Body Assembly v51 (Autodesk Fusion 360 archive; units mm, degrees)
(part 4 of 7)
sketch "Sketch22" plane through (0, 0, 30.35) normal (0, 0, 1) x axis (-1, 0, 0)
  line L1 (-73.525, 79.5) -> (-73.525, 184)
  line L2 (-59.525, 79.5) -> (-73.525, 79.5)
  line L3 (-59.525, 174.475) -> (-59.525, 79.5)
  line L4 (1.475, 174.475) -> (-59.525, 174.475)
  line L5 (1.475, 79.5) -> (1.475, 174.475)
  line L6 (37.7, 79.5) -> (1.475, 79.5)
  line L7 (37.7, 158.6) -> (37.7, 79.5)
  line L8 (-84.3454, 196.7) -> (-0.4, 196.7)
  line L9 (-122.4454, 79.5) -> (-122.4454, 158.6)
  line L10 (-109.7454, 79.5) -> (-122.4454, 79.5)
  line L11 (-109.7454, 158.6) -> (-109.7454, 79.5)
  line L12 (-73.525, 184) -> (-84.3454, 184)
  line L13 (-59.525, 18.175) -> (-109.7454, 18.175)
  line L14 (-59.525, 79.5) -> (-59.525, 18.175)
  line L15 (-122.4454, 79.5) -> (-59.525, 79.5)
  line L16 (-122.4454, 0.3904) -> (-122.4454, 79.5)
  line L17 (-0.4, -37.7096) -> (-84.3454, -37.7096)
  line L18 (37.7, 79.5) -> (37.7, 0.3904)
  line L19 (1.475, 79.5) -> (37.7, 79.5)
  line L20 (1.475, 18.175) -> (1.475, 79.5)
  line L21 (25, 18.175) -> (1.475, 18.175)
  line L22 (25, 0.3904) -> (25, 18.175)
  line L23 (-84.3454, -25.0096) -> (-0.4, -25.0096)
  line L24 (-109.7454, 18.175) -> (-109.7454, 0.3904)
  line L25 (-0.4, 190.35) -> (-84.35, 190.35)
  line L26 (14.4492, 185.5408) -> (15.1755, 186.267)
  line L27 (27.267, 174.1755) -> (26.5408, 173.4492)
  line L28 (31.35, 116.35) -> (31.35, 158.6)
  line L29 (29.15, 116.35) -> (31.35, 116.35)
  line L30 (31.35, 99.25) -> (29.15, 99.25)
  line L31 (31.35, 79.5) -> (31.35, 99.25)
  line L32 (37.7, 79.5) -> (31.35, 79.5)
  line L33 (37.7, 158.6) -> (37.7, 79.5)
  line L34 (-84.35, 196.7) -> (-0.4, 196.7)
  line L35 (-122.45, 79.5) -> (-122.45, 158.6)
  line L36 (-116.1, 79.5) -> (-122.45, 79.5)
  line L37 (-116.1, 99.25) -> (-116.1, 79.5)
  line L38 (-113.9, 99.25) -> (-116.1, 99.25)
  line L39 (-116.1, 116.35) -> (-113.9, 116.35)
  line L40 (-116.1, 158.6) -> (-116.1, 116.35)
  line L41 (-111.2908, 173.4492) -> (-112.017, 174.1755)
  line L42 (-99.9255, 186.267) -> (-99.1992, 185.5408)
  line L43 (-116.1, 79.5) -> (-116.1, 59.75)
  line L44 (-122.45, 79.5) -> (-116.1, 79.5)
  line L45 (-122.45, 0.4) -> (-122.45, 79.5)
  line L46 (-0.4, -37.7) -> (-84.35, -37.7)
  line L47 (37.7, 79.5) -> (37.7, 0.4)
  line L48 (31.35, 79.5) -> (37.7, 79.5)
  line L49 (31.35, 59.75) -> (31.35, 79.5)
  line L50 (29.15, 59.75) -> (31.35, 59.75)
  line L51 (31.35, 42.65) -> (29.15, 42.65)
  line L52 (31.35, 0.4) -> (31.35, 42.65)
  line L53 (26.5408, -14.4492) -> (27.267, -15.1755)
  line L54 (15.1755, -27.267) -> (14.4492, -26.5408)
  line L55 (-84.35, -31.35) -> (-0.4, -31.35)
  line L56 (-99.1992, -26.5408) -> (-99.9255, -27.267)
  line L57 (-112.017, -15.1755) -> (-111.2908, -14.4492)
  line L58 (-116.1, 42.65) -> (-116.1, 0.4)
  line L59 (-113.9, 42.65) -> (-116.1, 42.65)
  line L60 (-116.1, 59.75) -> (-113.9, 59.75)
  arc A1 centre (-0.4, 158.6) radius 38.1 clockwise from (-0.4, 196.7) to (37.7, 158.6)
  arc A2 centre (-84.3454, 158.6) radius 38.1 clockwise from (-122.4454, 158.6) to (-84.3454, 196.7)
  arc A3 centre (-84.3454, 158.6) radius 25.4 clockwise from (-109.7454, 158.6) to (-84.3454, 184)
  arc A4 centre (-113.9, 107.8) radius 8.55 clockwise from (-113.9, 116.35) to (-113.9, 99.25)
  arc A5 centre (-105.245, 179.495) radius 8.55 clockwise from (-99.1992, 185.5408) to (-111.2908, 173.4492)
  arc A6 centre (-105.245, -20.495) radius 8.55 clockwise from (-111.2908, -14.4492) to (-99.1992, -26.5408)
  arc A7 centre (20.495, -20.495) radius 8.55 clockwise from (14.4492, -26.5408) to (26.5408, -14.4492)
  arc A8 centre (-84.3454, 0.3904) radius 38.1 clockwise from (-84.3454, -37.7096) to (-122.4454, 0.3904)
  arc A9 centre (-0.4, 0.3904) radius 38.1 clockwise from (37.7, 0.3904) to (-0.4, -37.7096)
  arc A10 centre (-0.4, 0.3904) radius 25.4 clockwise from (25, 0.3904) to (-0.4, -25.0096)
  arc A11 centre (-84.3454, 0.3904) radius 25.4 clockwise from (-84.3454, -25.0096) to (-109.7454, 0.3904)
  circle C1 centre (-105.245, 179.495) radius 2.2
  circle C2 centre (20.495, 179.495) radius 2.2
  circle C3 centre (-113.9, 107.8) radius 2.2
  circle C4 centre (29.15, 107.8) radius 2.2
  arc A12 centre (-84.35, 158.6) radius 31.75 clockwise from (-99.9255, 186.267) to (-84.35, 190.35)
  arc A13 centre (-0.4, 158.6) radius 31.75 clockwise from (-0.4, 190.35) to (15.1755, 186.267)
  arc A14 centre (20.495, 179.495) radius 8.55 clockwise from (26.5408, 173.4492) to (14.4492, 185.5408)
  arc A15 centre (-0.4, 158.6) radius 31.75 clockwise from (27.267, 174.1755) to (31.35, 158.6)
  arc A16 centre (29.15, 107.8) radius 8.55 clockwise from (29.15, 99.25) to (29.15, 116.35)
  arc A17 centre (-0.4, 158.6) radius 38.1 clockwise from (-0.4, 196.7) to (37.7, 158.6)
  arc A18 centre (-84.35, 158.6) radius 38.1 clockwise from (-122.45, 158.6) to (-84.35, 196.7)
  arc A19 centre (-113.9, 107.8) radius 8.55 clockwise from (-113.9, 116.35) to (-113.9, 99.25)
  arc A20 centre (-84.35, 158.6) radius 31.75 clockwise from (-116.1, 158.6) to (-112.017, 174.1755)
  arc A21 centre (-105.245, 179.495) radius 8.55 clockwise from (-99.1992, 185.5408) to (-111.2908, 173.4492)
  arc A22 centre (-84.35, 0.4) radius 38.1 clockwise from (-84.35, -37.7) to (-122.45, 0.4)
  arc A23 centre (-0.4, 0.4) radius 38.1 clockwise from (37.7, 0.4) to (-0.4, -37.7)
  arc A24 centre (29.15, 51.2) radius 8.55 clockwise from (29.15, 42.65) to (29.15, 59.75)
  arc A25 centre (-0.4, 0.4) radius 31.75 clockwise from (31.35, 0.4) to (27.267, -15.1755)
  arc A26 centre (20.495, -20.495) radius 8.55 clockwise from (14.4492, -26.5408) to (26.5408, -14.4492)
  arc A27 centre (-0.4, 0.4) radius 31.75 clockwise from (15.1755, -27.267) to (-0.4, -31.35)
  arc A28 centre (-84.35, 0.4) radius 31.75 clockwise from (-84.35, -31.35) to (-99.9255, -27.267)
  arc A29 centre (-105.245, -20.495) radius 8.55 clockwise from (-111.2908, -14.4492) to (-99.1992, -26.5408)
  arc A30 centre (-84.35, 0.4) radius 31.75 clockwise from (-112.017, -15.1755) to (-116.1, 0.4)
  arc A31 centre (-113.9, 51.2) radius 8.55 clockwise from (-113.9, 59.75) to (-113.9, 42.65)
  circle C5 centre (-105.245, -20.495) radius 2.2
  circle C6 centre (20.495, -20.495) radius 2.2
  circle C7 centre (29.15, 51.2) radius 2.2
  circle C8 centre (-113.9, 51.2) radius 2.2
extrude "Extrude44" add sketch "Sketch22" profile of L11 A3 A4 A5 A6 A7 A10 A11 against normal blind 6.35
hole "Hole5" HoleDepth 10.0076 HoleDiameter 3.4 (= "m3screwdiam") TipAngle 180
position "Position22"
sketch "Sketch23" plane through (0, 0, -1.65) normal (0, 0, 1) x axis (-1, 0, 0)
  line L1 (-113.9, 59.75) -> (-116.1, 59.75)
  line L2 (-116.1, 42.65) -> (-113.9, 42.65)
  line L3 (-116.1, 0.4) -> (-116.1, 42.65)
  line L4 (-111.2908, -14.4492) -> (-112.017, -15.1755)
  line L5 (-99.9255, -27.267) -> (-99.1992, -26.5408)
  line L6 (-0.4, -31.35) -> (-84.35, -31.35)
  line L7 (14.4492, -26.5408) -> (15.1755, -27.267)
  line L8 (27.267, -15.1755) -> (26.5408, -14.4492)
  line L9 (31.35, 42.65) -> (31.35, 0.4)
  line L10 (29.15, 42.65) -> (31.35, 42.65)
  line L11 (31.35, 59.75) -> (29.15, 59.75)
  line L12 (31.35, 79.5) -> (31.35, 59.75)
  line L13 (-116.1, 79.5) -> (31.35, 79.5)
  line L14 (-116.1, 59.75) -> (-116.1, 79.5)
  line L15 (4.625, 25) -> (9.125, 20.5)
  line L16 (-36.375, 25) -> (4.625, 25)
  line L17 (-40.875, 20.5) -> (-36.375, 25)
  line L18 (-40.875, -20.5) -> (-40.875, 20.5)
  line L19 (-36.375, -25) -> (-40.875, -20.5)
  line L20 (4.625, -25) -> (-36.375, -25)
  line L21 (9.125, -20.5) -> (4.625, -25)
  line L22 (9.125, 20.5) -> (9.125, -20.5)
  line L23 (4.625, 78) -> (9.125, 73.5)
  line L24 (-36.375, 78) -> (4.625, 78)
  line L25 (-40.875, 73.5) -> (-36.375, 78)
  line L26 (-40.875, 32.5) -> (-40.875, 73.5)
  line L27 (-36.375, 28) -> (-40.875, 32.5)
  line L28 (4.625, 28) -> (-36.375, 28)
  line L29 (9.125, 32.5) -> (4.625, 28)
  line L30 (9.125, 73.5) -> (9.125, 32.5)
  line L31 (-48.375, 78) -> (-43.875, 73.5)
  line L32 (-89.375, 78) -> (-48.375, 78)
  line L33 (-93.875, 73.5) -> (-89.375, 78)
  line L34 (-93.875, 32.5) -> (-93.875, 73.5)
  line L35 (-89.375, 28) -> (-93.875, 32.5)
  line L36 (-48.375, 28) -> (-89.375, 28)
  line L37 (-43.875, 32.5) -> (-48.375, 28)
  line L38 (-43.875, 73.5) -> (-43.875, 32.5)
  line L39 (-48.375, 131) -> (-43.875, 126.5)
  line L40 (-89.375, 131) -> (-48.375, 131)
  line L41 (-93.875, 126.5) -> (-89.375, 131)
  line L42 (-93.875, 85.5) -> (-93.875, 126.5)
  line L43 (-89.375, 81) -> (-93.875, 85.5)
  line L44 (-48.375, 81) -> (-89.375, 81)
  line L45 (-43.875, 85.5) -> (-48.375, 81)
  line L46 (-43.875, 126.5) -> (-43.875, 85.5)
  line L47 (4.625, 131) -> (9.125, 126.5)
  line L48 (-36.375, 131) -> (4.625, 131)
  line L49 (-40.875, 126.5) -> (-36.375, 131)
  line L50 (-40.875, 85.5) -> (-40.875, 126.5)
  line L51 (-36.375, 81) -> (-40.875, 85.5)
  line L52 (4.625, 81) -> (-36.375, 81)
  line L53 (9.125, 85.5) -> (4.625, 81)
  line L54 (9.125, 126.5) -> (9.125, 85.5)
  line L55 (-48.375, 184) -> (-43.875, 179.5)
  line L56 (-89.375, 184) -> (-48.375, 184)
  line L57 (-93.875, 179.5) -> (-89.375, 184)
  line L58 (-93.875, 138.5) -> (-93.875, 179.5)
  line L59 (-89.375, 134) -> (-93.875, 138.5)
  line L60 (-48.375, 134) -> (-89.375, 134)
  line L61 (-43.875, 138.5) -> (-48.375, 134)
  line L62 (-43.875, 179.5) -> (-43.875, 138.5)
  line L63 (4.625, 184) -> (9.125, 179.5)
  line L64 (-36.375, 184) -> (4.625, 184)
  line L65 (-40.875, 179.5) -> (-36.375, 184)
  line L66 (-40.875, 138.5) -> (-40.875, 179.5)
  line L67 (-36.375, 134) -> (-40.875, 138.5)
  line L68 (4.625, 134) -> (-36.375, 134)
  line L69 (9.125, 138.5) -> (4.625, 134)
  line L70 (9.125, 179.5) -> (9.125, 138.5)
  line L71 (-48.375, 25) -> (-43.875, 20.5)
  line L72 (-89.375, 25) -> (-48.375, 25)
  line L73 (-93.875, 20.5) -> (-89.375, 25)
  line L74 (-93.875, -20.5) -> (-93.875, 20.5)
  line L75 (-89.375, -25) -> (-93.875, -20.5)
  line L76 (-48.375, -25) -> (-89.375, -25)
  line L77 (-43.875, -20.5) -> (-48.375, -25)
  line L78 (-43.875, 20.5) -> (-43.875, -20.5)
  arc A1 centre (-113.9, 51.2) radius 8.55 clockwise from (-113.9, 59.75) to (-113.9, 42.65)
  arc A2 centre (-84.35, 0.4) radius 31.75 clockwise from (-112.017, -15.1755) to (-116.1, 0.4)
  arc A3 centre (-105.245, -20.495) radius 8.55 clockwise from (-111.2908, -14.4492) to (-99.1992, -26.5408)
  arc A4 centre (-84.35, 0.4) radius 31.75 clockwise from (-84.35, -31.35) to (-99.9255, -27.267)
  arc A5 centre (-0.4, 0.4) radius 31.75 clockwise from (15.1755, -27.267) to (-0.4, -31.35)
  arc A6 centre (20.495, -20.495) radius 8.55 clockwise from (14.4492, -26.5408) to (26.5408, -14.4492)
  arc A7 centre (-0.4, 0.4) radius 31.75 clockwise from (31.35, 0.4) to (27.267, -15.1755)
  arc A8 centre (29.15, 51.2) radius 8.55 clockwise from (29.15, 42.65) to (29.15, 59.75)
  circle C1 centre (-35.875, -20) radius 1.5
  circle C2 centre (-35.875, 20) radius 1.5
  circle C3 centre (4.125, -20) radius 1.5
  circle C4 centre (4.125, 20) radius 1.5
  circle C5 centre (-29.625, 0) radius 1.5
  circle C6 centre (-2.125, 0) radius 1.5
  circle C7 centre (-35.875, 33) radius 1.5
  circle C8 centre (-35.875, 73) radius 1.5
  circle C9 centre (4.125, 33) radius 1.5
  circle C10 centre (4.125, 73) radius 1.5
  circle C11 centre (-29.625, 53) radius 1.5
  circle C12 centre (-2.125, 53) radius 1.5
  circle C13 centre (-88.875, 33) radius 1.5
  circle C14 centre (-88.875, 73) radius 1.5
  circle C15 centre (-48.875, 33) radius 1.5
  circle C16 centre (-48.875, 73) radius 1.5
  circle C17 centre (-82.625, 53) radius 1.5
  circle C18 centre (-55.125, 53) radius 1.5
  circle C19 centre (-88.875, 86) radius 1.5
  circle C20 centre (-88.875, 126) radius 1.5
  circle C21 centre (-48.875, 86) radius 1.5
  circle C22 centre (-48.875, 126) radius 1.5
  circle C23 centre (-82.625, 106) radius 1.5
  circle C24 centre (-55.125, 106) radius 1.5
  circle C25 centre (-35.875, 86) radius 1.5
  circle C26 centre (-35.875, 126) radius 1.5
  circle C27 centre (4.125, 86) radius 1.5
  circle C28 centre (4.125, 126) radius 1.5
  circle C29 centre (-29.625, 106) radius 1.5
  circle C30 centre (-2.125, 106) radius 1.5
  circle C31 centre (-88.875, 139) radius 1.5
  circle C32 centre (-88.875, 179) radius 1.5
  circle C33 centre (-48.875, 139) radius 1.5
  circle C34 centre (-48.875, 179) radius 1.5
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hole "Hole6" HoleDepth 38.1 HoleDiameter 4.4 (= "threadedinsertdiam") TipAngle 180
sketch "Sketch25" plane through (0, 0, 30.35) normal (0, 0, 1) x axis (-1, 0, 0)
  line L1 (-73.525, 79.5) -> (-73.525, 184)
  line L2 (-59.525, 79.5) -> (-73.525, 79.5)
  line L3 (-59.525, 174.475) -> (-59.525, 79.5)
  line L4 (1.475, 174.475) -> (-59.525, 174.475)
  line L5 (1.475, 79.5) -> (1.475, 174.475)
  line L6 (37.7, 79.5) -> (1.475, 79.5)
  line L7 (37.7, 158.6) -> (37.7, 79.5)
  line L8 (-84.3454, 196.7) -> (-0.4, 196.7)
  line L9 (-122.4454, 79.5) -> (-122.4454, 158.6)
  line L10 (-109.7454, 79.5) -> (-122.4454, 79.5)
  line L11 (-109.7454, 100.3273) -> (-109.7454, 79.5)
  line L12 (-109.7454, 158.6) -> (-109.7454, 115.2727)
  line L13 (-73.525, 184) -> (-84.3454, 184)
  circle C1 centre (-105.245, 179.495) radius 1.7
  circle C2 centre (20.495, 179.495) radius 1.7
  circle C3 centre (29.15, 107.8) radius 1.7
  circle C4 centre (-113.9, 107.8) radius 1.7
  arc A1 centre (-0.4, 158.6) radius 38.1 clockwise from (-0.4, 196.7) to (37.7, 158.6)
  arc A2 centre (-84.3454, 158.6) radius 38.1 clockwise from (-122.4454, 158.6) to (-84.3454, 196.7)
  arc A3 centre (-113.9, 107.8) radius 8.55 clockwise from (-109.7454, 115.2727) to (-109.7454, 100.3273)
  arc A4 centre (-84.3454, 158.6) radius 25.4 clockwise from (-109.7454, 158.6) to (-106.4925, 171.0365)
  arc A5 centre (-105.245, 179.495) radius 8.55 clockwise from (-96.7868, 180.7443) to (-106.4925, 171.0365)
  arc A6 centre (-84.3454, 158.6) radius 25.4 clockwise from (-96.7868, 180.7443) to (-84.3454, 184)
  circle C5 centre (7.825, 148.425) radius 1.5
  circle C6 centre (-65.875, 148.425) radius 1.5
  circle C7 centre (-65.875, 96.325) radius 1.5
  circle C8 centre (7.825, 96.325) radius 1.5
  circle C9 centre (7.825, 44.225) radius 1.5
  circle C10 centre (-65.875, 44.225) radius 1.5
hole "Hole7" HoleDepth 22.86 HoleDiameter 4.4 (= "threadedinsertdiam") TipAngle 180
move "Move1"
extrude "Extrude48" new body of existing geometry blind 19.05
extrude "Extrude49" new body of existing geometry blind 16.51
combine "Combine10"
combine "Combine11"
mirror "Mirror6" mirrorStitchTolerance 0.1016
mirror "Mirror7" mirrorStitchTolerance 0.1016
combine "Combine12"
combine "Combine13"
sketch "Sketch26" plane through (0, 0, 30.35) normal (0, 0, -1) x axis (1, 0, 0)
  line L1 (113.9, 116.35) -> (116.1, 116.35)
  line L2 (116.1, 99.25) -> (113.9, 99.25)
  line L3 (116.1, 79.5) -> (116.1, 99.25)
  line L4 (122.45, 79.5) -> (116.1, 79.5)
  line L5 (122.45, 158.6) -> (122.45, 79.5)
  line L6 (0.4, 196.7) -> (84.35, 196.7)
  line L7 (-37.7, 79.5) -> (-37.7, 158.6)
  line L8 (-31.35, 79.5) -> (-37.7, 79.5)
  line L9 (-31.35, 99.25) -> (-31.35, 79.5)
  line L10 (-29.15, 99.25) -> (-31.35, 99.25)
  line L11 (-31.35, 116.35) -> (-29.15, 116.35)
  line L12 (-31.35, 158.6) -> (-31.35, 116.35)
  line L13 (-26.5408, 173.4492) -> (-27.267, 174.1755)
  line L14 (-15.1755, 186.267) -> (-14.4492, 185.5408)
  line L15 (84.35, 190.35) -> (0.4, 190.35)
  line L16 (99.1992, 185.5408) -> (99.9255, 186.267)
  line L17 (112.017, 174.1755) -> (111.2908, 173.4492)
  line L18 (116.1, 116.35) -> (116.1, 158.6)
  line L19 (113.9, 59.75) -> (116.1, 59.75)
  line L20 (116.1, 42.65) -> (113.9, 42.65)
  line L21 (116.1, 0.4) -> (116.1, 42.65)
  line L22 (111.2908, -14.4492) -> (112.017, -15.1755)
  line L23 (99.9255, -27.267) -> (99.1992, -26.5408)
  line L24 (0.4, -31.35) -> (84.35, -31.35)
  line L25 (-14.4492, -26.5408) -> (-15.1755, -27.267)
  line L26 (-27.267, -15.1755) -> (-26.5408, -14.4492)
  line L27 (-31.35, 42.65) -> (-31.35, 0.4)
  line L28 (-29.15, 42.65) -> (-31.35, 42.65)
  line L29 (-31.35, 59.75) -> (-29.15, 59.75)
  line L30 (-31.35, 79.5) -> (-31.35, 59.75)
  line L31 (-37.7, 79.5) -> (-31.35, 79.5)
  line L32 (-37.7, 0.4) -> (-37.7, 79.5)
  line L33 (84.35, -37.7) -> (0.4, -37.7)
  line L34 (122.45, 79.5) -> (122.45, 0.4)
  line L35 (116.1, 79.5) -> (122.45, 79.5)
  line L36 (116.1, 59.75) -> (116.1, 79.5)
  circle C1 centre (113.9, 107.8) radius 2.2
  circle C2 centre (105.245, 179.495) radius 2.2
  circle C3 centre (-20.495, 179.495) radius 2.2
  arc A1 centre (113.9, 107.8) radius 8.55 clockwise from (113.9, 99.25) to (113.9, 116.35)
  arc A2 centre (84.35, 158.6) radius 38.1 clockwise from (84.35, 196.7) to (122.45, 158.6)
  arc A3 centre (0.4, 158.6) radius 38.1 clockwise from (-37.7, 158.6) to (0.4, 196.7)
  arc A4 centre (-29.15, 107.8) radius 8.55 clockwise from (-29.15, 116.35) to (-29.15, 99.25)
  arc A5 centre (0.4, 158.6) radius 31.75 clockwise from (-31.35, 158.6) to (-27.267, 174.1755)
  arc A6 centre (-20.495, 179.495) radius 8.55 clockwise from (-14.4492, 185.5408) to (-26.5408, 173.4492)
  arc A7 centre (0.4, 158.6) radius 31.75 clockwise from (-15.1755, 186.267) to (0.4, 190.35)
  arc A8 centre (84.35, 158.6) radius 31.75 clockwise from (84.35, 190.35) to (99.9255, 186.267)
  arc A9 centre (105.245, 179.495) radius 8.55 clockwise from (111.2908, 173.4492) to (99.1992, 185.5408)
  arc A10 centre (84.35, 158.6) radius 31.75 clockwise from (112.017, 174.1755) to (116.1, 158.6)
  circle C4 centre (-29.15, 107.8) radius 2.2
  circle C5 centre (113.9, 51.2) radius 2.2
  circle C6 centre (105.245, -20.495) radius 2.2
  circle C7 centre (-20.495, -20.495) radius 2.2
  circle C8 centre (-29.15, 51.2) radius 2.2
  arc A11 centre (113.9, 51.2) radius 8.55 clockwise from (113.9, 42.65) to (113.9, 59.75)
  arc A12 centre (84.35, 0.4) radius 31.75 clockwise from (116.1, 0.4) to (112.017, -15.1755)
  arc A13 centre (105.245, -20.495) radius 8.55 clockwise from (99.1992, -26.5408) to (111.2908, -14.4492)
  arc A14 centre (84.35, 0.4) radius 31.75 clockwise from (99.9255, -27.267) to (84.35, -31.35)
  arc A15 centre (0.4, 0.4) radius 31.75 clockwise from (0.4, -31.35) to (-15.1755, -27.267)
  arc A16 centre (-20.495, -20.495) radius 8.55 clockwise from (-26.5408, -14.4492) to (-14.4492, -26.5408)
  arc A17 centre (0.4, 0.4) radius 31.75 clockwise from (-27.267, -15.1755) to (-31.35, 0.4)
  arc A18 centre (-29.15, 51.2) radius 8.55 clockwise from (-29.15, 59.75) to (-29.15, 42.65)
  arc A19 centre (0.4, 0.4) radius 38.1 clockwise from (0.4, -37.7) to (-37.7, 0.4)
  arc A20 centre (84.35, 0.4) radius 38.1 clockwise from (122.45, 0.4) to (84.35, -37.7)
extrude "Extrude50" cut sketch "Sketch26" profile of C1 C2 C3 C4 C5 C6 C7 C8 against normal blind 165.1
component_from_bodies "Body->Comp1"
copy_paste_bodies "CutPasteBodies1"
component_from_bodies "Body->Comp2"
component_from_bodies "Body->Comp3"
copy_paste_bodies "CutPasteBodies1"
copy_paste_bodies "CutPasteBodies1"
component_from_bodies "Body->Comp4"
copy_paste_bodies "CutPasteBodies1"
copy_paste "CutPaste1"
copy_paste "CutPaste1"
copy_paste "CutPaste2"
copy_paste "CutPaste3"
copy_paste "CutPaste4"
sketch "Sketch27" plane through (122.45, 0, 0) normal (1, 0, 0) x axis (0, 1, 0)
  line L1 (-0.4, 30.35) -> (-79.5, 30.35)
  line L2 (-0.4, 55.75) -> (-0.4, 30.35)
  line L3 (-79.5, 55.75) -> (-0.4, 55.75)
  line L4 (-79.5, 30.35) -> (-79.5, 55.75)
  line L5 (-79.5, -8) -> (-79.5, 24)
  line L6 (-0.4, -8) -> (-79.5, -8)
  line L7 (-0.4, 24) -> (-0.4, -8)
  line L8 (-79.5, 24) -> (-0.4, 24)
  line L9 (-79.5, 24) -> (-79.5, -8)
  line L10 (-158.6, 24) -> (-79.5, 24)
  line L11 (-158.6, -8) -> (-158.6, 24)
  line L12 (-79.5, -8) -> (-158.6, -8)
  line L13 (-79.5, 30.35) -> (-158.6, 30.35)
  line L14 (-79.5, 55.75) -> (-79.5, 30.35)
  line L15 (-158.6, 55.75) -> (-79.5, 55.75)
  line L16 (-158.6, 30.35) -> (-158.6, 55.75)
  circle C1 centre (-50.925, 41.7349) radius 2.2
  circle C2 centre (-69.975, 41.7349) radius 2.2
  circle C3 centre (-69.975, 11.175) radius 2.2
  circle C4 centre (-50.925, 11.175) radius 2.2
  circle C5 centre (-108.075, 11.175) radius 2.2
  circle C6 centre (-89.025, 11.175) radius 2.2
  circle C7 centre (-89.025, 41.7349) radius 2.2
  circle C8 centre (-108.075, 41.7349) radius 2.2
sketch "Sketch28" plane through (-37.7, 0, 0) normal (-1, 0, 0) x axis (0, -1, 0)
  line L1 (79.5, 24) -> (79.5, -8)
  line L2 (0.4, 24) -> (79.5, 24)
  line L3 (0.4, -8) -> (0.4, 24)
  line L4 (79.5, -8) -> (0.4, -8)
  line L5 (79.5, 30.35) -> (0.4, 30.35)
  line L6 (79.5, 55.75) -> (79.5, 30.35)
  line L7 (0.4, 55.75) -> (79.5, 55.75)
  line L8 (0.4, 30.35) -> (0.4, 55.75)
  line L9 (79.5, 30.35) -> (79.5, 55.75)
  line L10 (158.6, 30.35) -> (79.5, 30.35)
  line L11 (158.6, 55.75) -> (158.6, 30.35)
  line L12 (156.8611, 55.75) -> (158.6, 55.75)
  line L13 (156.8611, 39.65) -> (156.8611, 55.75)
  line L14 (136.6611, 39.65) -> (156.8611, 39.65)
  line L15 (136.6611, 55.75) -> (136.6611, 39.65)
  line L16 (79.5, 55.75) -> (136.6611, 55.75)
  line L17 (79.5, -8) -> (79.5, 24)
  line L18 (158.6, -8) -> (79.5, -8)
  line L19 (158.6, 24) -> (158.6, -8)
  line L20 (79.5, 24) -> (158.6, 24)
  circle C1 centre (69.975, 11.175) radius 2.2
  circle C2 centre (50.925, 11.175) radius 2.2
  circle C3 centre (50.925, 41.7349) radius 2.2
  circle C4 centre (69.975, 41.7349) radius 2.2
  circle C5 centre (89.025, 41.7349) radius 2.2
  circle C6 centre (108.075, 41.7349) radius 2.2
  circle C7 centre (108.075, 11.175) radius 2.2
  circle C8 centre (89.025, 11.175) radius 2.2
sketch "Sketch29" plane through (0, 0, 62.1) normal (0, 0, 1) x axis (-1, 0, 0)
  line L1 (-116.1, 79.5) -> (-116.1, 107.8)
  line L2 (31.35, 79.5) -> (-116.1, 79.5)
  line L3 (31.35, 107.8) -> (31.35, 79.5)
  line L4 (31.35, 158.6) -> (31.35, 107.8)
  line L5 (-84.35, 190.35) -> (-0.4, 190.35)
  line L6 (-116.1, 107.8) -> (-116.1, 158.6)
  line L7 (-116.1, 0.4) -> (-116.1, 51.2)
  line L8 (-0.4, -31.35) -> (-84.35, -31.35)
  line L9 (31.35, 51.2) -> (31.35, 0.4)
  line L10 (31.35, 79.5) -> (31.35, 51.2)
  line L11 (-116.1, 79.5) -> (31.35, 79.5)
  line L12 (-116.1, 51.2) -> (-116.1, 79.5)
  line L13 (-80.29, 14.65) -> (-84.35, 14.65)
  line L14 (-80.29, 4.35) -> (-80.29, 14.65)
  line L15 (-84.35, 4.35) -> (-80.29, 4.35)
  line L16 (-84.35, 14.65) -> (-84.35, 4.35)
  line L17 (-80.29, -8.35) -> (-84.35, -8.35)
  line L18 (-80.29, -18.65) -> (-80.29, -8.35)
  line L19 (-84.35, -18.65) -> (-80.29, -18.65)
  line L20 (-84.35, -8.35) -> (-84.35, -18.65)
  line L21 (-68.8771, 14.65) -> (-72.9371, 14.65)
  line L22 (-68.8771, 4.35) -> (-68.8771, 14.65)
  line L23 (-72.9371, 4.35) -> (-68.8771, 4.35)
  line L24 (-72.9371, 14.65) -> (-72.9371, 4.35)
  line L25 (-68.8771, -8.35) -> (-72.9371, -8.35)
  line L26 (-68.8771, -18.65) -> (-68.8771, -8.35)
  line L27 (-72.9371, -18.65) -> (-68.8771, -18.65)
  line L28 (-72.9371, -8.35) -> (-72.9371, -18.65)
  line L29 (-57.4643, 14.65) -> (-61.5243, 14.65)
  line L30 (-57.4643, 4.35) -> (-57.4643, 14.65)
  line L31 (-61.5243, 4.35) -> (-57.4643, 4.35)
  line L32 (-61.5243, 14.65) -> (-61.5243, 4.35)
  line L33 (-57.4643, -8.35) -> (-61.5243, -8.35)
  line L34 (-57.4643, -18.65) -> (-57.4643, -8.35)
  line L35 (-61.5243, -18.65) -> (-57.4643, -18.65)
  line L36 (-61.5243, -8.35) -> (-61.5243, -18.65)
  line L37 (-46.0514, 14.65) -> (-50.1114, 14.65)
  line L38 (-46.0514, 4.35) -> (-46.0514, 14.65)
  line L39 (-50.1114, 4.35) -> (-46.0514, 4.35)
  line L40 (-50.1114, 14.65) -> (-50.1114, 4.35)
  line L41 (-46.0514, -8.35) -> (-50.1114, -8.35)
  line L42 (-46.0514, -18.65) -> (-46.0514, -8.35)
  line L43 (-50.1114, -18.65) -> (-46.0514, -18.65)
  line L44 (-50.1114, -8.35) -> (-50.1114, -18.65)
  line L45 (-34.6386, 14.65) -> (-38.6986, 14.65)
  line L46 (-34.6386, 4.35) -> (-34.6386, 14.65)
  line L47 (-38.6986, 4.35) -> (-34.6386, 4.35)
  line L48 (-38.6986, 14.65) -> (-38.6986, 4.35)
  line L49 (-34.6386, -8.35) -> (-38.6986, -8.35)
  line L50 (-34.6386, -18.65) -> (-34.6386, -8.35)
  line L51 (-38.6986, -18.65) -> (-34.6386, -18.65)
  line L52 (-38.6986, -8.35) -> (-38.6986, -18.65)
  line L53 (-23.2257, 14.65) -> (-27.2857, 14.65)
  line L54 (-23.2257, 4.35) -> (-23.2257, 14.65)
  line L55 (-27.2857, 4.35) -> (-23.2257, 4.35)
  line L56 (-27.2857, 14.65) -> (-27.2857, 4.35)
  line L57 (-23.2257, -8.35) -> (-27.2857, -8.35)
  line L58 (-23.2257, -18.65) -> (-23.2257, -8.35)
  line L59 (-27.2857, -18.65) -> (-23.2257, -18.65)
  line L60 (-27.2857, -8.35) -> (-27.2857, -18.65)
  line L61 (-11.8129, 14.65) -> (-15.8729, 14.65)
  line L62 (-11.8129, 4.35) -> (-11.8129, 14.65)
  line L63 (-15.8729, 4.35) -> (-11.8129, 4.35)
  line L64 (-15.8729, 14.65) -> (-15.8729, 4.35)
  line L65 (-11.8129, -8.35) -> (-15.8729, -8.35)
  line L66 (-11.8129, -18.65) -> (-11.8129, -8.35)
  line L67 (-15.8729, -18.65) -> (-11.8129, -18.65)
  line L68 (-15.8729, -8.35) -> (-15.8729, -18.65)
  line L69 (-0.4, 14.65) -> (-4.46, 14.65)
  line L70 (-0.4, 4.35) -> (-0.4, 14.65)
  line L71 (-4.46, 4.35) -> (-0.4, 4.35)
  line L72 (-4.46, 14.65) -> (-4.46, 4.35)
  line L73 (-0.4, -8.35) -> (-4.46, -8.35)
  line L74 (-0.4, -18.65) -> (-0.4, -8.35)
  line L75 (-4.46, -18.65) -> (-0.4, -18.65)
  line L76 (-4.46, -8.35) -> (-4.46, -18.65)
  circle C1 centre (29.15, 107.8) radius 2.2
  arc A1 centre (-0.4, 158.6) radius 31.75 clockwise from (22.0506, 181.0506) to (31.35, 158.6)
  circle C2 centre (20.495, 179.495) radius 2.2
  arc A2 centre (-0.4, 158.6) radius 31.75 clockwise from (-0.4, 190.35) to (22.0506, 181.0506)
  arc A3 centre (-84.35, 158.6) radius 31.75 clockwise from (-106.8006, 181.0506) to (-84.35, 190.35)
  circle C3 centre (-105.245, 179.495) radius 2.2
  arc A4 centre (-84.35, 158.6) radius 31.75 clockwise from (-116.1, 158.6) to (-106.8006, 181.0506)
  circle C4 centre (-113.9, 107.8) radius 2.2
  arc A5 centre (-84.35, 0.4) radius 31.75 clockwise from (-106.8006, -22.0506) to (-116.1, 0.4)
  circle C5 centre (-105.245, -20.495) radius 2.2
  arc A6 centre (-84.35, 0.4) radius 31.75 clockwise from (-84.35, -31.35) to (-106.8006, -22.0506)
  arc A7 centre (-0.4, 0.4) radius 31.75 clockwise from (22.0506, -22.0506) to (-0.4, -31.35)
  circle C6 centre (20.495, -20.495) radius 2.2
  arc A8 centre (-0.4, 0.4) radius 31.75 clockwise from (31.35, 0.4) to (22.0506, -22.0506)
  circle C7 centre (29.15, 51.2) radius 2.2
  circle C8 centre (-113.9, 51.2) radius 2.2
delete_face "DeleteFace1"
hole "Hole1" HoleDepth 38.1 HoleDiameter 3.4 (= "m3screwdiam") TipAngle 180
delete_face "DeleteFace2"
delete_face "DeleteFace1"
delete_face "DeleteFace3"
delete_face "DeleteFace4"
delete_face "DeleteFace5"
offset_faces "OffsetFaces1" distance -2.794
sketch "Sketch1" plane through (0, 0, 0) normal (0, 0, 1) x axis (1, 0, 0)
  circle C1 centre (0, 0) radius 2.45
  circle C2 centre (0, 0) radius 1.5
  circle C3 centre (0, 0) radius 1.95
  point P1 (0, 0)
  point P2 (0, 0)
  coincident P1 P2
  concentric C1 C2
  concentric C1 C3
  dimension "d1_1" diameter C1 = 4.9
  dimension "d2_1" diameter C2 = 3
  dimension "d3_1" diameter C3 = 3.9
extrude "Extrude1" new body sketch "Sketch1" distance 0.7 (= "( 1.4 / 2 ) * 1 mm") named "d4_1"
extrude "Extrude2" add sketch "Sketch1" profile of C2 C3 distance 3.3 (= "5 mm - 1.7 mm") named "d6_1"
extrude "Extrude3" of existing geometry blind 1.7 named "d9_1"
extrude "Extrude4" add of existing geometry blind 1.7 named "d11_1"
mirror "Mirror1" mirrorStitchTolerance 0.1 named "d14_1"
extrude "Extrude5" new body sketch "Sketch1" profile of C2 C3 distance 3 named "d15_1"
extrude "Extrude6" sketch "Sketch1" blind -1.8 named "d18_1"
mirror "Mirror2" mirrorStitchTolerance 0.1 named "d21_1"
move "Move1"
component_from_bodies "Body->Comp1"
component_from_bodies "Body->Comp2"
position "Position23"
copy_paste_bodies "CopyPasteBodies1"
move "Move2"
copy_paste_bodies "CopyPasteBodies2"
move "Move3"
copy_paste_bodies "CopyPasteBodies3"
move "Move4"
align "Align1"
align "Align2"
align "Align3"
copy_paste_bodies "CutPasteBodies1"
rectangular_pattern "R-Pattern1" uSpaceDistance -53 vSpaceDistance 0
copy_paste_bodies "CopyPasteBodies2"
move "Move1"
align "Align1"
copy_paste_bodies "CopyPasteBodies4"
move "Move5"
copy_paste_bodies "CopyPasteBodies5"
move "Move6"
copy_paste_bodies "CopyPasteBodies6"
move "Move7"
align "Align4"
align "Align5"
align "Align6"
copy_paste_bodies "CutPasteBodies1"
mirror "Mirror1" mirrorStitchTolerance 0.1016
copy_paste_bodies "CopyPasteBodies7"
move "Move8"
align "Align7"
copy_paste_bodies "CopyPasteBodies8"
move "Move9"
copy_paste_bodies "CopyPasteBodies9"
move "Move10"
copy_paste_bodies "CopyPasteBodies10"
move "Move11"
align "Align8"
align "Align9"
align "Align10"
mirror "Mirror8" mirrorStitchTolerance 0.1016
copy_paste_bodies "CutPasteBodies3"
position "Position24"
extrude "Extrude3" add of existing geometry blind 6.4516
extrude "Extrude4" add of existing geometry blind 6.35
position "Position25"
sketch "Sketch30" plane through (0, 0, 30.35) normal (0, 0, 1) x axis (-1, 0, 0)
  line L1 (-73.525, 79.5) -> (-73.525, 184)
  line L2 (-59.525, 79.5) -> (-73.525, 79.5)
  line L3 (-59.525, 174.475) -> (-59.525, 79.5)
  line L4 (1.475, 174.475) -> (-59.525, 174.475)
  line L5 (1.475, 79.5) -> (1.475, 174.475)
  line L6 (37.7, 79.5) -> (1.475, 79.5)
  line L7 (37.7, 158.6) -> (37.7, 79.5)
  line L8 (-84.3454, 196.7) -> (-0.4, 196.7)
  line L9 (-122.4454, 79.5) -> (-122.4454, 158.6)
  line L10 (-109.7454, 79.5) -> (-122.4454, 79.5)
  line L11 (-109.7454, 100.3273) -> (-109.7454, 79.5)
  line L12 (-109.7454, 158.6) -> (-109.7454, 115.2727)
  line L13 (-73.525, 184) -> (-84.3454, 184)
  line L14 (-59.525, 18.175) -> (-109.7454, 18.175)
  line L15 (-59.525, 79.5) -> (-59.525, 18.175)
  line L16 (-122.4454, 79.5) -> (-59.525, 79.5)
  line L17 (-122.4454, 0.3904) -> (-122.4454, 79.5)
  line L18 (-0.4, -37.7096) -> (-84.3454, -37.7096)
  line L19 (37.7, 79.5) -> (37.7, 0.3904)
  line L20 (1.475, 79.5) -> (37.7, 79.5)
  line L21 (1.475, 18.175) -> (1.475, 79.5)
  line L22 (25, 18.175) -> (1.475, 18.175)
  line L23 (25, 0.3904) -> (25, 18.175)
  line L24 (-84.3454, -25.0096) -> (-0.4, -25.0096)
  line L25 (-109.7454, 18.175) -> (-109.7454, 0.3904)
  line L26 (-73.525, 31.525) -> (-59.525, 31.525)
  line L27 (-73.525, 161.125) -> (-73.525, 31.525)
  line L28 (-59.525, 161.125) -> (-73.525, 161.125)
  line L29 (-59.525, 31.525) -> (-59.525, 161.125)
  circle C1 centre (7.825, 148.425) radius 2.2
  circle C2 centre (7.825, 96.325) radius 2.2
  circle C3 centre (-65.875, 148.425) radius 2.2
  circle C4 centre (-65.875, 96.325) radius 2.2
  circle C5 centre (-105.245, 179.495) radius 1.7
  circle C6 centre (20.495, 179.495) radius 1.7
  circle C7 centre (29.15, 107.8) radius 1.7
  circle C8 centre (-113.9, 107.8) radius 1.7
  arc A1 centre (-0.4, 158.6) radius 38.1 clockwise from (-0.4, 196.7) to (37.7, 158.6)
  arc A2 centre (-84.3454, 158.6) radius 38.1 clockwise from (-122.4454, 158.6) to (-84.3454, 196.7)
  arc A3 centre (-113.9, 107.8) radius 8.55 clockwise from (-109.7454, 115.2727) to (-109.7454, 100.3273)
  arc A4 centre (-84.3454, 158.6) radius 25.4 clockwise from (-109.7454, 158.6) to (-106.4925, 171.0365)
  arc A5 centre (-105.245, 179.495) radius 8.55 clockwise from (-96.7868, 180.7443) to (-106.4925, 171.0365)
  arc A6 centre (-84.3454, 158.6) radius 25.4 clockwise from (-96.7868, 180.7443) to (-84.3454, 184)
  circle C9 centre (-65.875, 44.225) radius 2.2
  circle C10 centre (7.825, 44.225) radius 2.2
  circle C11 centre (20.495, -20.495) radius 1.7
  circle C12 centre (-113.9, 51.2) radius 1.7
  circle C13 centre (-105.245, -20.495) radius 1.7
  circle C14 centre (29.15, 51.2) radius 1.7
  arc A7 centre (-84.3454, 0.3904) radius 38.1 clockwise from (-84.3454, -37.7096) to (-122.4454, 0.3904)
  arc A8 centre (-0.4, 0.3904) radius 38.1 clockwise from (37.7, 0.3904) to (-0.4, -37.7096)
  arc A9 centre (-0.4, 0.3904) radius 25.4 clockwise from (25, 0.3904) to (21.7517, -12.0379)
  arc A10 centre (20.495, -20.495) radius 8.55 clockwise from (12.0384, -21.7556) to (21.7517, -12.0379)
  arc A11 centre (-0.4, 0.3904) radius 25.4 clockwise from (12.0384, -21.7556) to (-0.4, -25.0096)
  arc A12 centre (-84.3454, 0.3904) radius 25.4 clockwise from (-84.3454, -25.0096) to (-96.7881, -21.7532)
  arc A13 centre (-105.245, -20.495) radius 8.55 clockwise from (-106.4975, -12.0372) to (-96.7881, -21.7532)
  arc A14 centre (-84.3454, 0.3904) radius 25.4 clockwise from (-106.4975, -12.0372) to (-109.7454, 0.3904)
  point P61 (-73.525, 161.125)
  point P59 (-59.525, 31.525)
  point P4 (-65.875, 148.425)
  point P31 (-65.875, 44.225)
  horizontal L26
  vertical L27
  horizontal L28
  vertical L29
  coincident L1 P61
  coincident L15 P59
  dimension "d270" distance P4 L28 = 12.7
  dimension "d271" distance P31 L26 = 12.7
extrude "Extrude51" new body sketch "Sketch30" profile of C3 C4 L1 L2 L3 C9 L15 L16 L26 L27 L28 L29 along normal blind 6.35
hole "Hole8" HoleDepth 38.1 HoleDiameter 3.4 (= "m3screwdiam") TipAngle 180
fillet "Fillet5" radius 3.175
work_plane "WorkPlane8"
mirror "Mirror9" mirrorStitchTolerance 0.1016
rectangular_pattern "R-Pattern2" uSpaceDistance 36.9099 vSpaceDistance 0
copy_paste "CutPaste2"
base_feature "Base Feature1"
base_feature "Base Feature1"
remove_instance "RemoveInstance1"
move_face "MoveFace2"
move_face "MoveFace1"
align "Align2"
copy_paste_bodies "CopyPasteBodies11"
move "Move12"
copy_paste_bodies "CopyPasteBodies12"
move "Move13"
copy_paste_bodies "CopyPasteBodies13"
move "Move14"
align "Align11"
align "Align12"
align "Align13"
copy_paste_bodies "CutPasteBodies1"
copy_paste_bodies "CutPasteBodies2"
copy_paste "CutPaste3"
rectangular_pattern "R-Pattern1" uSpaceDistance 36.9099 vSpaceDistance 0
mirror "Mirror1" mirrorStitchTolerance 0.1016
copy_paste_bodies "CopyPasteBodies14"
move "Move15"
align "Align14"
offset_faces "OffsetFaces1" distance 4
component_from_bodies "Body->Comp5"
rectangular_pattern "R-Pattern1" uSpaceDistance -52.1 vSpaceDistance 0
mirror "Mirror1" mirrorStitchTolerance 0.1016
copy_paste "CutPaste1"
copy_paste_bodies "CopyPasteBodies4"
move "Move2"
align "Align2"
rectangular_pattern "R-Pattern3" uSpaceDistance -52.1 vSpaceDistance 0
mirror "Mirror2" mirrorStitchTolerance 0.1016
component_from_bodies "Body->Comp1"
copy_paste_bodies "CutPasteBodies1"
copy_paste "CutPaste5"
copy_paste_bodies "CopyPasteBodies15"
move "Move16"
align "Align15"
offset_faces "OffsetFaces2" distance -4
component_from_bodies "Body->Comp6"
copy_paste "CutPaste2"
copy_paste_bodies "CopyPasteBodies16"
move "Move17"
copy_paste_bodies "CopyPasteBodies17"
move "Move18"
copy_paste_bodies "CopyPasteBodies18"
move "Move19"
align "Align16"
align "Align17"
align "Align18"
copy_paste_bodies "CutPasteBodies1"
rectangular_pattern "R-Pattern1" uSpaceDistance 53 vSpaceDistance 0
rectangular_pattern "R-Pattern2" uSpaceDistance 53 vSpaceDistance 0
copy_paste_bodies "CopyPasteBodies19"
move "Move20"
offset_faces "OffsetFaces3" distance 45
component_from_bodies "Body->Comp7"
copy_paste "CutPaste3"
copy_paste_bodies "CopyPasteBodies20"
move "Move21"
move "Move22"
sketch "Sketch31" plane through (0, -117.6, 0) normal (0, -1, 0) x axis (1, 0, 0)
  line L1 (108.35, 68.45) -> (108.35, 74.8)
  line L2 (116.1, 68.45) -> (108.35, 68.45)
  line L3 (122.45, 62.1) -> (116.1, 68.45)
  line L4 (122.45, -8) -> (122.45, 62.1)
  line L5 (128.8, -8) -> (122.45, -8)
  line L6 (128.8, 64.7303) -> (128.8, -8)
  line L7 (118.7303, 74.8) -> (128.8, 64.7303)
  line L8 (108.35, 74.8) -> (118.7303, 74.8)
  line L9 (130.6327, 62.1) -> (122.45, 62.1)
  point P5 (122.45, 62.1)
  point P10 (122.45, 62.1)
  coincident P5 P10
  perpendicular L6 L9
split "Split1"
remove_body "RemoveBody3"
remove_body "RemoveBody4"
align "Align19"
align "Align1"
copy_paste_bodies "CutPasteBodies1"
mirror "Mirror1" mirrorStitchTolerance 0.1016
mirror "Mirror2" mirrorStitchTolerance 0.1016
sketch "Sketch32" plane through (0, 0, 68.45) normal (0, 0, 1) x axis (-1, 0, 0)
  line L1 (-116.1, 0.4) -> (-116.1, 79.5)
  line L2 (-0.4, -31.35) -> (-84.35, -31.35)
  line L3 (31.35, 79.5) -> (31.35, 0.4)
  line L4 (-116.1, 79.5) -> (31.35, 79.5)
  line L5 (-80.29, 14.65) -> (-84.35, 14.65)
  line L6 (-80.29, 4.35) -> (-80.29, 14.65)
  line L7 (-84.35, 4.35) -> (-80.29, 4.35)
  line L8 (-84.35, 14.65) -> (-84.35, 4.35)
  line L9 (-80.29, -8.35) -> (-84.35, -8.35)
  line L10 (-80.29, -18.65) -> (-80.29, -8.35)
  line L11 (-84.35, -18.65) -> (-80.29, -18.65)
  line L12 (-84.35, -8.35) -> (-84.35, -18.65)
  line L13 (-68.8771, 14.65) -> (-72.9371, 14.65)
  line L14 (-68.8771, 4.35) -> (-68.8771, 14.65)
  line L15 (-72.9371, 4.35) -> (-68.8771, 4.35)
  line L16 (-72.9371, 14.65) -> (-72.9371, 4.35)
  line L17 (-68.8771, -8.35) -> (-72.9371, -8.35)
  line L18 (-68.8771, -18.65) -> (-68.8771, -8.35)
  line L19 (-72.9371, -18.65) -> (-68.8771, -18.65)
  line L20 (-72.9371, -8.35) -> (-72.9371, -18.65)
  line L21 (-57.4643, 14.65) -> (-61.5243, 14.65)
  line L22 (-57.4643, 4.35) -> (-57.4643, 14.65)
  line L23 (-61.5243, 4.35) -> (-57.4643, 4.35)
  line L24 (-61.5243, 14.65) -> (-61.5243, 4.35)
  line L25 (-57.4643, -8.35) -> (-61.5243, -8.35)
  line L26 (-57.4643, -18.65) -> (-57.4643, -8.35)
  line L27 (-61.5243, -18.65) -> (-57.4643, -18.65)
  line L28 (-61.5243, -8.35) -> (-61.5243, -18.65)
  line L29 (-46.0514, 14.65) -> (-50.1114, 14.65)
  line L30 (-46.0514, 4.35) -> (-46.0514, 14.65)
  line L31 (-50.1114, 4.35) -> (-46.0514, 4.35)
  line L32 (-50.1114, 14.65) -> (-50.1114, 4.35)
  line L33 (-46.0514, -8.35) -> (-50.1114, -8.35)
  line L34 (-46.0514, -18.65) -> (-46.0514, -8.35)
  line L35 (-50.1114, -18.65) -> (-46.0514, -18.65)
  line L36 (-50.1114, -8.35) -> (-50.1114, -18.65)
  line L37 (-34.6386, 14.65) -> (-38.6986, 14.65)
  line L38 (-34.6386, 4.35) -> (-34.6386, 14.65)
  line L39 (-38.6986, 4.35) -> (-34.6386, 4.35)
  line L40 (-38.6986, 14.65) -> (-38.6986, 4.35)
  line L41 (-34.6386, -8.35) -> (-38.6986, -8.35)
  line L42 (-34.6386, -18.65) -> (-34.6386, -8.35)
  line L43 (-38.6986, -18.65) -> (-34.6386, -18.65)
  line L44 (-38.6986, -8.35) -> (-38.6986, -18.65)
  line L45 (-23.2257, 14.65) -> (-27.2857, 14.65)
  line L46 (-23.2257, 4.35) -> (-23.2257, 14.65)
  line L47 (-27.2857, 4.35) -> (-23.2257, 4.35)
  line L48 (-27.2857, 14.65) -> (-27.2857, 4.35)
  line L49 (-23.2257, -8.35) -> (-27.2857, -8.35)
  line L50 (-23.2257, -18.65) -> (-23.2257, -8.35)
  line L51 (-27.2857, -18.65) -> (-23.2257, -18.65)
  line L52 (-27.2857, -8.35) -> (-27.2857, -18.65)
  line L53 (-11.8129, 14.65) -> (-15.8729, 14.65)
  line L54 (-11.8129, 4.35) -> (-11.8129, 14.65)
  line L55 (-15.8729, 4.35) -> (-11.8129, 4.35)
  line L56 (-15.8729, 14.65) -> (-15.8729, 4.35)
  line L57 (-11.8129, -8.35) -> (-15.8729, -8.35)
  line L58 (-11.8129, -18.65) -> (-11.8129, -8.35)
  line L59 (-15.8729, -18.65) -> (-11.8129, -18.65)
  line L60 (-15.8729, -8.35) -> (-15.8729, -18.65)
  line L61 (-0.4, 14.65) -> (-4.46, 14.65)
  line L62 (-0.4, 4.35) -> (-0.4, 14.65)
  line L63 (-4.46, 4.35) -> (-0.4, 4.35)
  line L64 (-4.46, 14.65) -> (-4.46, 4.35)
  line L65 (-0.4, -8.35) -> (-4.46, -8.35)
  line L66 (-0.4, -18.65) -> (-0.4, -8.35)
  line L67 (-4.46, -18.65) -> (-0.4, -18.65)
  line L68 (-4.46, -8.35) -> (-4.46, -18.65)
  line L69 (-113.4697, 158.6) -> (-113.4697, 116.3392)
  line L70 (-0.4, 187.7197) -> (-84.35, 187.7197)
  line L71 (28.7197, 156.8611) -> (28.7197, 158.6)
  line L72 (37.7, 156.8611) -> (28.7197, 156.8611)
  line L73 (37.7, 136.6611) -> (37.7, 156.8611)
  line L74 (28.7197, 136.6611) -> (37.7, 136.6611)
  line L75 (28.7197, 116.3392) -> (28.7197, 136.6611)
  line L76 (28.7197, 79.5) -> (28.7197, 99.2608)
  line L77 (-113.4697, 79.5) -> (28.7197, 79.5)
  line L78 (-113.4697, 99.2608) -> (-113.4697, 79.5)
  line L79 (-113.4697, 79.5) -> (-113.4697, 59.7392)
  line L80 (28.7197, 79.5) -> (-113.4697, 79.5)
  line L81 (28.7197, 59.7392) -> (28.7197, 79.5)
  line L82 (28.7197, 0.4) -> (28.7197, 42.6608)
  line L83 (5.95, 21) -> (5.95, -28.019)
  line L84 (-90.7, 21) -> (5.95, 21)
  line L85 (-90.7, -28.019) -> (-90.7, 21)
  line L86 (-113.4697, 42.6608) -> (-113.4697, 0.4)
  line L87 (-73.525, 79.5) -> (-73.525, 184)
  line L88 (-86.8399, -27.2809) -> (-86.8399, 79.5)
  line L89 (-86.8399, 210.1778) -> (-86.8399, 79.5)
  line L90 (-79.8399, 38.75) -> (-93.8399, 38.75)
  line L91 (-79.8399, 61.75) -> (-79.8399, 38.75)
  line L92 (-93.8399, 61.75) -> (-79.8399, 61.75)
  line L93 (-93.8399, 38.75) -> (-93.8399, 61.75)
  line L94 (-79.8399, 61.75) -> (-93.8399, 38.75)
  line L95 (-93.8399, 61.75) -> (-79.8399, 38.75)
  line L96 (-80.5899, 97.575) -> (-93.0899, 97.575)
  line L97 (-80.5899, 118.575) -> (-80.5899, 97.575)
  line L98 (-93.0899, 118.575) -> (-80.5899, 118.575)
  line L99 (-93.0899, 97.575) -> (-93.0899, 118.575)
  line L100 (-80.5899, 118.575) -> (-93.0899, 97.575)
  line L101 (-93.0899, 118.575) -> (-80.5899, 97.575)
  line L102 (-82.7649, 141.35) -> (-90.9149, 141.35)
  line L103 (-82.7649, 154.35) -> (-82.7649, 141.35)
  line L104 (-88.4149, 157.35) -> (-85.2649, 157.35)
  line L105 (-90.9149, 141.35) -> (-90.9149, 154.35)
  line L106 (-82.7649, 157.35) -> (-90.9149, 141.35)
  line L107 (-90.9149, 157.35) -> (-82.7649, 141.35)
  line L108 (-85.2649, 157.35) -> (-82.7649, 154.35)
  line L109 (-90.9149, 154.35) -> (-88.4149, 157.35)
  line L110 (-82.2907, 163.7) -> (-76.4149, 156.649)
  line L111 (-91.3891, 163.7) -> (-82.2907, 163.7)
  line L112 (-97.2649, 156.649) -> (-91.3891, 163.7)
  line L113 (-97.2649, 135) -> (-97.2649, 156.649)
  line L114 (-76.4149, 135) -> (-97.2649, 135)
  line L115 (-76.4149, 156.649) -> (-76.4149, 135)
  circle C1 centre (-105.245, -20.495) radius 1.7
  circle C2 centre (29.15, 51.2) radius 1.7
  circle C3 centre (20.495, -20.495) radius 1.7
  circle C4 centre (-113.9, 51.2) radius 1.7
  arc A1 centre (-84.35, 0.4) radius 31.75 clockwise from (-84.35, -31.35) to (-116.1, 0.4)
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  point P126 (-86.8399, 79.5)
  point P127 (-86.8399, 79.5)
  point P129 (-86.8399, 79.5)
  point P135 (-86.8399, 50.25)
  point P140 (-86.8399, 108.075)
  point P145 (-86.8399, 149.35)
  point P143 (-82.7649, 157.35)
  point P144 (-90.9149, 157.35)
  point P125 (-73.525, 79.5)
  point P131 (-93.8399, 38.75)
  point P132 (-79.8399, 38.75)
  point P134 (-93.8399, 61.75)
  point P136 (-93.0899, 97.575)
  point P139 (-93.0899, 118.575)
  point P137 (-80.5899, 97.575)
  point P141 (-90.9149, 141.35)
  point P146 (-82.7649, 154.35)
  point P147 (-85.2649, 157.35)
  point P148 (-88.4149, 157.35)
  point P149 (-90.9149, 154.35)
  coincident L77 P126
  coincident P126 P127
  perpendicular L4 L88
  coincident P126 P129
  perpendicular L4 L89
  horizontal L90
  perpendicular L90 L91
  parallel L90 L92
  parallel L91 L93
  coincident L94 P135
  coincident L95 P135
  coincident L88 P135
  horizontal L96
  perpendicular L96 L97
  parallel L96 L98
  parallel L97 L99
  coincident L100 P140
  coincident L101 P140
  coincident L89 P140
  horizontal L102
  perpendicular L102 L103
  parallel L102 L104
  parallel L103 L105
  coincident L106 P145
  coincident L107 P145
  coincident L89 P145
  coincident P143 L103
  coincident P143 L104
  coincident P144 L104
  coincident P144 L105
  dimension "d320" distance P125 P126 = 13.3149 (= "1.5726277117689287 in * 1 / 3")
  dimension "d321" distance P131 P132 = 14
  dimension "d322" distance P131 P134 = 23
  dimension "d323" distance L80 P135 = 29.25 (= "2.303149606299209 in / 2")
  dimension "d324" distance P136 P139 = 21
  dimension "d325" distance P136 P137 = 12.5
  dimension "d326" distance P141 P144 = 16
  dimension "d327" distance L103 L105 = 8.15
  dimension "d328" distance P143 P146 = 3
  dimension "d329" distance P143 P147 = 2.5
  dimension "d330" distance P144 P148 = 2.5 (= "d329")
  dimension "d331" distance P144 P149 = 3 (= "d328")
  dimension "d332" distance P126 P145 = 69.85
  dimension "d333" distance L80 P140 = 28.575
  dimension "d334" = 6.35
extrude "Extrude5" cut sketch "Sketch32" profile of L90 L91 L92 L93 L96 L97 L98 L99 against normal blind 33.02
extrude "Extrude6" cut sketch "Sketch32" profile of L102 L103 L104 L105 L108 L109 against normal blind 38.1
extrude "Extrude7" add sketch "Sketch32" profile of L102 L103 L104 L105 L108 L109 L114 L113 L110 L111 L112 L115 against normal blind 16
delete_face "DeleteFace5"
delete_face "DeleteFace6"
sketch "Sketch33" plane through (0, 0, 24) normal (0, 0, 1) x axis (-1, 0, 0)
  line L1 (-116.1, 79.5) -> (-116.1, 59.75)
  line L2 (-122.45, 79.5) -> (-116.1, 79.5)
  line L3 (-122.45, 0.4) -> (-122.45, 79.5)
  line L4 (-0.4, -37.7) -> (-84.35, -37.7)
  line L5 (37.7, 79.5) -> (37.7, 0.4)
  line L6 (31.35, 79.5) -> (37.7, 79.5)
  line L7 (31.35, 59.75) -> (31.35, 79.5)
  line L8 (29.15, 59.75) -> (31.35, 59.75)
  line L9 (31.35, 42.65) -> (29.15, 42.65)
  line L10 (31.35, 0.4) -> (31.35, 42.65)
  line L11 (26.5408, -14.4492) -> (27.267, -15.1755)
  line L12 (15.1755, -27.267) -> (14.4492, -26.5408)
  line L13 (-84.35, -31.35) -> (-0.4, -31.35)
  line L14 (-99.1992, -26.5408) -> (-99.9255, -27.267)
  line L15 (-112.017, -15.1755) -> (-111.2908, -14.4492)
  line L16 (-116.1, 42.65) -> (-116.1, 0.4)
  line L17 (-113.9, 42.65) -> (-116.1, 42.65)
  line L18 (-116.1, 59.75) -> (-113.9, 59.75)
  arc A1 centre (-84.35, 0.4) radius 38.1 clockwise from (-84.35, -37.7) to (-122.45, 0.4)
  arc A2 centre (-0.4, 0.4) radius 38.1 clockwise from (37.7, 0.4) to (-0.4, -37.7)
  arc A3 centre (29.15, 51.2) radius 8.55 clockwise from (29.15, 42.65) to (29.15, 59.75)
  arc A4 centre (-0.4, 0.4) radius 31.75 clockwise from (31.35, 0.4) to (27.267, -15.1755)
  arc A5 centre (20.495, -20.495) radius 8.55 clockwise from (14.4492, -26.5408) to (26.5408, -14.4492)
  arc A6 centre (-0.4, 0.4) radius 31.75 clockwise from (15.1755, -27.267) to (-0.4, -31.35)
  arc A7 centre (-84.35, 0.4) radius 31.75 clockwise from (-84.35, -31.35) to (-99.9255, -27.267)
  arc A8 centre (-105.245, -20.495) radius 8.55 clockwise from (-111.2908, -14.4492) to (-99.1992, -26.5408)
  arc A9 centre (-84.35, 0.4) radius 31.75 clockwise from (-112.017, -15.1755) to (-116.1, 0.4)
  arc A10 centre (-113.9, 51.2) radius 8.55 clockwise from (-113.9, 59.75) to (-113.9, 42.65)
  circle C1 centre (-105.245, -20.495) radius 2.2
  circle C2 centre (20.495, -20.495) radius 2.2
hole "Hole1" HoleDepth 12.446 HoleDiameter 4.4 (= "threadedinsertdiam") TipAngle 180
chamfer "Chamfer1" distance 2.6303
chamfer "Chamfer2" distance 6.35
sketch "Sketch34" plane through (0, 0, 62.1) normal (0, 0, 1) x axis (-1, 0, 0)
  line L1 (44.05, 117.6) -> (44.05, 41.4)
  line L2 (37.7, 41.4) -> (37.7, 117.6)
  line L3 (44.05, 41.4) -> (37.7, 41.4)
  line L4 (44.05, 117.6) -> (44.05, 41.4)
  line L5 (37.7, 117.6) -> (44.05, 117.6)
  line L6 (37.7, 41.4) -> (37.7, 117.6)
  line L7 (44.05, 41.4) -> (37.7, 41.4)
  line L8 (37.7, 117.6) -> (44.05, 117.6)
  horizontal L3
  vertical L4
  horizontal L5
  vertical L6
sketch "Sketch35" plane through (0, -117.6, 0) normal (0, -1, 0) x axis (1, 0, 0)
  line L1 (-37.7, 62.1) -> (-37.7, -8)
  line L2 (-44.05, -8) -> (-44.05, 62.1)
  line L3 (116.1, 68.45) -> (122.45, 62.1)
  line L4 (-31.35, 68.45) -> (116.1, 68.45)
  line L5 (-37.7, 62.1) -> (-31.35, 68.45)
  line L6 (118.7303, 74.8) -> (126.9401, 66.5901)
  line L7 (-33.9803, 74.8) -> (118.7303, 74.8)
  line L8 (-42.1901, 66.5901) -> (-33.9803, 74.8)
  line L9 (-42.1901, 66.5901) -> (-37.7, 62.1)
  line L10 (126.9401, 66.5901) -> (122.45, 62.1)
  line L11 (-44.05, 62.1) -> (-37.7, 62.1)
  line L12 (-37.7, -8) -> (-44.05, -8)
  point P9 (122.45, 62.1)
  point P10 (122.45, 62.1)
  point P8 (116.1, 68.45)
  point P11 (116.1, 68.45)
  point P7 (-31.35, 68.45)
  point P12 (-31.35, 68.45)
  point P6 (-37.7, 62.1)
  point P13 (-37.7, 62.1)
  point P18 (-37.7, 62.1)
  coincident P9 P10
  coincident P8 P11
  coincident P7 P12
  coincident P6 P13
  coincident P6 P18
  perpendicular L8 L9
  dimension "d357" distance L3 = 6.35
move "Move1"
extrude "Extrude52" new body sketch "Sketch35" profile of L3 L4 L5 L6 L7 L8 L9 L10 against normal blind 76.2
component_from_bodies "Body->Comp8"
copy_paste "CutPaste6"
copy_paste_bodies "CutPasteBodies3"
remove_instance "RemoveInstance1"
combine "Combine1"
delete_face "DeleteFace1"
combine "Combine2"
delete_face "DeleteFace2"
work_plane "WorkPlane9" AlongDistance -6.35
split "Split2"
offset_faces "OffsetFaces4" distance -0.1
offset_faces "OffsetFaces5" distance -0.3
